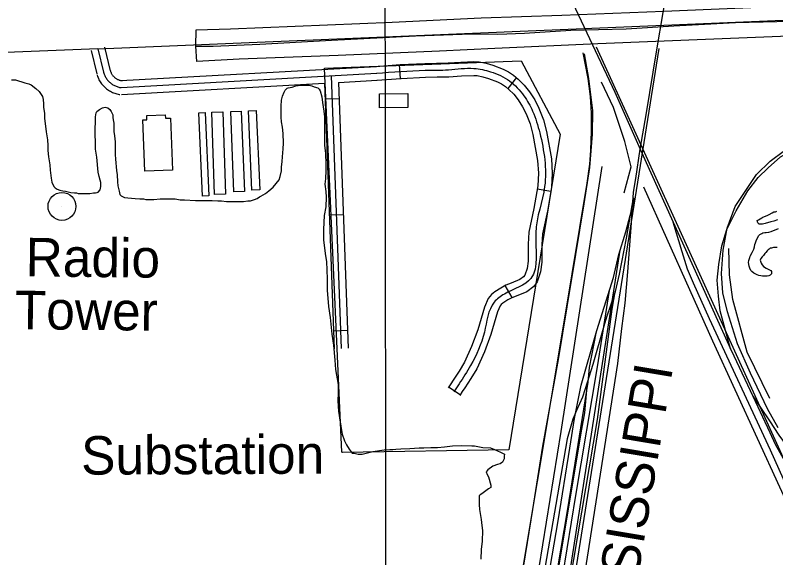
# Model space of a CAD drawing. Extents: x 3313442 to 3351311, y 721974 to 747360.
# Drawn here: x 3327267 to 3328908, y 733684 to 734854 of the extents above; entities that cross this region are included whole.
import ezdxf

# ---------------------------------------------------------------- set-up
doc = ezdxf.new("R2010")
doc.units = 0
for name, color, linetype in [('V-BLDG-OTLN', 7, 'Continuous'), ('V-BRDG-OTLN', 7, 'Continuous'), ('V-GRID-MAJR', 7, 'Continuous'), ('V-RAIL-IDEN', 7, 'Continuous'), ('V-RAIL-TRAK', 7, 'Continuous'), ('V-ROAD-CNTR', 7, 'Continuous'), ('V-SITE-OTLN', 7, 'Continuous'), ('V-SITE-OTLN-IDEN', 7, 'Continuous'), ('V-SITE-VEGE', 7, 'Continuous'), ('V-TOPO-SHOR', 7, 'Continuous'), ('V-TOPO-TOWR', 7, 'Continuous'), ('V-TOPO-TOWR-IDEN', 7, 'Continuous')]:
    doc.layers.add(name, color=color, linetype=linetype)

msp = doc.modelspace()

# ---------------------------------------------------------------- linework, layer by layer
at = {"layer": 'V-BLDG-OTLN'}
for points in [[(3328114, 734684.9), (3328114.2, 734654.7), (3328052.9, 734654.2), (3328052.7, 734684.4)], [(3327546.9, 734517.8), (3327542.7, 734628.2), (3327551.1, 734628.5), (3327550.7, 734637.5), (3327590.9, 734639.1), (3327591.2, 734631.5), (3327602, 734631.9), (3327606.3, 734520.1)], [(3327670.8, 734463.6), (3327662.9, 734643.6), (3327676.7, 734644.2), (3327684.5, 734464.2)], [(3327697, 734467.4), (3327691.5, 734644.6), (3327715.3, 734645.3), (3327720.8, 734468.1)], [(3327738.9, 734473.1), (3327732, 734646.4), (3327754.8, 734647.3), (3327761.8, 734474)], [(3327777.5, 734476.8), (3327770.1, 734647.8), (3327787.2, 734648.5), (3327794.6, 734477.6)]]:
    msp.add_lwpolyline(points, close=True, dxfattribs=at)
at = {"layer": 'V-BRDG-OTLN'}
msp.add_lwpolyline([(3329200.4, 734803.9), (3329188.2, 734806.1), (3329102.4, 734812.3), (3328989.8, 734811), (3328774.2, 734802.1), (3328523.7, 734792.1), (3328302, 734782), (3328182.3, 734776.6), (3327963.6, 734766.7), (3327750.4, 734759.3), (3327658.7, 734754.3), (3327656.9, 734786.7), (3327657.2, 734821.9), (3327731.8, 734824.5), (3328080.2, 734838.7), (3328272.4, 734847.9), (3328446.3, 734853.9), (3328666.4, 734862.3), (3328887.9, 734871.5), (3329054.7, 734876), (3329202.8, 734875.2), (3329202.4, 734839.7)], close=True, dxfattribs=at)
msp.add_lwpolyline([(3327657, 734786.7), (3327663.3, 734787), (3327694.3, 734787), (3327794.7, 734791.3), (3327949.7, 734800.3), (3328130.6, 734809), (3328251.3, 734813.3), (3328308.1, 734813.2), (3328365.7, 734815), (3328465.8, 734821.5), (3328585, 734824.7), (3328687.6, 734830.8), (3328821.2, 734837.7), (3328910.2, 734840.5), (3328975.9, 734841.5), (3329049.7, 734843.6), (3329118, 734842.1), (3329191.5, 734840.1), (3329202.2, 734839.7)], dxfattribs=at)
at = {"layer": 'V-GRID-MAJR'}
msp.add_spline([(3328075.1, 727366.3), (3328067.1, 733424.9), (3328059.2, 739486.7), (3328051.3, 745548.5), (3328051.3, 745551.5)], degree=3, dxfattribs=at)
at = {"layer": 'V-RAIL-TRAK'}
msp.add_line((3328555.1, 734220.1), (3328561, 734257.6), dxfattribs=at)
for points in [[(3328599.8, 734460.5), (3328600.7, 734472.2), (3328605.9, 734501.7), (3328615.5, 734565), (3328628.9, 734643.6), (3328650.8, 734774.6), (3328680.6, 734953.6), (3328726.3, 735228.9), (3328788, 735605.3), (3328838.6, 735905.7), (3328862.8, 736058.5), (3328890.3, 736217.5)], [(3328445.4, 734932.1), (3328560.7, 734688), (3328615.5, 734565), (3328638.3, 734513.7), (3328686.7, 734407.4), (3328723.4, 734326.8), (3328810.3, 734135)], [(3328193.5, 732625.7), (3328212.7, 732754.8), (3328229.5, 732857.7), (3328364.5, 733672.5), (3328452.6, 734200.6), (3328500.9, 734491.4), (3328506.5, 734532.8), (3328508.8, 734562.6), (3328510.3, 734603.6), (3328510, 734642.4), (3328507.8, 734678.2), (3328503.4, 734717.3), (3328492.4, 734772.7)], [(3328810.3, 734135), (3328787.8, 734216.3), (3328784.2, 734248.4), (3328781.7, 734282.7), (3328784.7, 734316.7), (3328791.7, 734356.9), (3328802.1, 734391.6), (3328822.1, 734432.1), (3328847.6, 734474.9), (3328870.1, 734503.7), (3328891.6, 734524.7), (3328917.8, 734548.3), (3328954, 734568.5), (3328990.9, 734584.7), (3329023.8, 734595.4), (3329047.1, 734599.4), (3329081.8, 734603.8), (3329124.2, 734607.5), (3329394.8, 734613.8)], [(3328307.8, 732543.9), (3328314.9, 732589), (3328364.3, 732880.5), (3328424.7, 733228.1), (3328483.2, 733566.1), (3328567, 734102.8), (3328576, 734178.4), (3328582.7, 734233.4), (3328589, 734300.6), (3328596.5, 734406.5), (3328598.8, 734446), (3328599.8, 734460.5)], [(3328599.8, 734460.5), (3328585, 734373.4), (3328570.1, 734295.5), (3328561.2, 734258.3), (3328561, 734257.6), (3328542.7, 734202.9), (3328537.1, 734183.8), (3328513, 734101.1), (3328501, 734062.1)], [(3329141.2, 733378.9), (3329128.8, 733406.2), (3329027.6, 733624.4), (3328896.2, 733916.2), (3328765.1, 734199.1), (3328730.1, 734275.9), (3328717.6, 734306.2), (3328705.5, 734343.5), (3328686.7, 734407.4)], [(3328203.5, 732092.2), (3328226.4, 732216.7), (3328228.8, 732229.9), (3328244.4, 732323.6), (3328261.5, 732426.6), (3328323.3, 732818.5), (3328429.4, 733429.6), (3328523.1, 733982.4), (3328555.1, 734220.1)], [(3328810.3, 734135), (3328817.2, 734119.6), (3328858.3, 734032.5)], [(3328501, 734062.1), (3328491.2, 734030.2), (3328478.2, 734001.7), (3328469.7, 733983.3), (3328457.6, 733940.9), (3328295.7, 733004.8), (3328243.2, 732687.4), (3328233.9, 732532.7), (3328228.6, 732476.2), (3328224, 732410), (3328223.8, 732406.5), (3328219.2, 732330.5), (3328214.3, 732253), (3328213.4, 732239.7)], [(3328501, 734062.1), (3328495, 733996.4), (3328489, 733961.3), (3328369.3, 733245.8), (3328276.3, 732676), (3328224, 732410)], [(3328858.3, 734032.5), (3328895.3, 733954.2), (3328906.3, 733929.5)], [(3328858.3, 734032.5), (3328894.4, 733979.3), (3328914.7, 733948.3), (3328936.1, 733919.1), (3328956.7, 733892.1), (3328981.4, 733867), (3329007.6, 733845.5), (3329033.8, 733826.3), (3329055.2, 733811.2), (3329083.6, 733793), (3329107.5, 733779), (3329139.3, 733763.1), (3329171, 733750.8), (3329200.9, 733740.5), (3329234.5, 733731.2), (3329270.6, 733723.8), (3329300.5, 733718.9), (3329335.9, 733716.3), (3329368.4, 733713.3), (3329492.1, 733718.3), (3329775.2, 733728)], [(3328906.3, 733929.5), (3328960.7, 733833), (3329108.3, 733519.1), (3329139.6, 733452.6), (3329184.5, 733353.3), (3329343.2, 733006.1), (3329494.1, 732673.4), (3329502.6, 732652), (3329513.6, 732622.4), (3329533.5, 732564.1), (3329539.4, 732532.7)]]:
    msp.add_lwpolyline(points, dxfattribs=at)
at = {"layer": 'V-ROAD-CNTR'}
for p, q in [((3328095.1, 734747.1), (3328097.3, 734717.2)), ((3328348.3, 734719.5), (3328329.5, 734696)), ((3327965.5, 734673.6), (3327935.5, 734672.5)), ((3328422.5, 734473.9), (3328393, 734479.1)), ((3327974.6, 734423.8), (3327944.7, 734422.7)), ((3328339.1, 734245.1), (3328324.3, 734271.2)), ((3327983.7, 734174), (3327953.8, 734172.9)), ((3328227.1, 734035.6), (3328202.1, 734052.3))]:
    msp.add_line(p, q, dxfattribs=at)
for points in [[(3327445.3, 734781.4), (3329181.9, 734853.6)], [(3327445.3, 734781.4), (3325663.8, 734710.1), (3324415, 734655.9)], [(3327445.3, 734781.4), (3327457.6, 734730.7)], [(3327459.9, 734785), (3327472.1, 734734.2)], [(3327896.4, 730170.4), (3328023.8, 730890.7), (3328416, 733278.4), (3328655.9, 734782.1)], [(3329577.9, 732463.1), (3328589, 734637), (3328521.3, 734784.9)], [(3327430.7, 734777.9), (3327443, 734727.2)], [(3328494.4, 734770.4), (3328503.7, 734717.6), (3328512.4, 734648.4), (3328511.6, 734597.4), (3328505.7, 734525.7), (3328493.6, 734447.1), (3328475.5, 734338.2), (3328456.7, 734225), (3328438.1, 734112), (3328404.6, 733924.8), (3328383.2, 733788.7), (3328352.4, 733597.3)], [(3328045.2, 734743.5), (3328097.8, 734747.3), (3328150.7, 734750), (3328176.2, 734750.7), (3328201.4, 734751.3), (3328228.5, 734752.7), (3328256.6, 734754.2), (3328267.6, 734753.6), (3328283, 734750.4), (3328297.6, 734746), (3328320, 734737.3), (3328331.3, 734731.4), (3328342.2, 734724.3), (3328352.3, 734716.2), (3328365.3, 734703.2), (3328376.6, 734688.8), (3328387.7, 734671.6), (3328397, 734653.3), (3328406.4, 734628.6), (3328413.4, 734603.2), (3328423.7, 734544), (3328425.6, 734513.4), (3328424.1, 734482.9), (3328415, 734431.6), (3328404.9, 734382.2), (3328403.3, 734359.2), (3328403.3, 734321.5), (3328400.5, 734300.6), (3328393, 734279.4), (3328385.8, 734268.8), (3328370.8, 734257.6), (3328348, 734248.5), (3328338.4, 734244.7), (3328330.1, 734240), (3328319.1, 734233), (3328315.6, 734230.1), (3328313.4, 734227.4), (3328307.4, 734214.3), (3328293.4, 734165.9), (3328279.4, 734128.3), (3328262.7, 734091.6), (3328250, 734070.6), (3328237.2, 734050.9), (3328231.6, 734042.4), (3328225.9, 734033.9)], [(3327471.9, 734735.1), (3327472.4, 734733.5), (3327472.8, 734732.3), (3327473.3, 734731.1), (3327473.8, 734730), (3327474.4, 734728.8), (3327475, 734727.7), (3327475.7, 734726.6), (3327476.4, 734725.5), (3327477.2, 734724.5), (3327478, 734723.4), (3327478.8, 734722.5), (3327479.7, 734721.5), (3327480.6, 734720.6), (3327481.6, 734719.8), (3327482.6, 734719), (3327483.6, 734718.2), (3327484.7, 734717.4), (3327485.8, 734716.8), (3327486.9, 734716.1), (3327488, 734715.5), (3327489.2, 734715), (3327490.4, 734714.5), (3327491.6, 734714), (3327492.8, 734713.6), (3327494.1, 734713.3), (3327495.3, 734713), (3327496.6, 734712.7), (3327497.7, 734712.6)], [(3327494.6, 734712.7), (3328046.1, 734743.5)], [(3327443.2, 734726.3), (3327443.9, 734724.2), (3327444.7, 734721.8), (3327445.7, 734719.4), (3327446.7, 734717.1), (3327447.8, 734714.8), (3327449.1, 734712.6), (3327450.4, 734710.4), (3327451.8, 734708.3), (3327453.3, 734706.2), (3327454.9, 734704.3), (3327456.6, 734702.3), (3327458.3, 734700.5), (3327460.1, 734698.7), (3327462, 734697), (3327464, 734695.4), (3327466, 734693.9), (3327468.1, 734692.4), (3327470.3, 734691.1), (3327472.5, 734689.8), (3327474.7, 734688.6), (3327477, 734687.5), (3327479.4, 734686.6), (3327481.8, 734685.7), (3327484.2, 734684.9), (3327486.6, 734684.2), (3327489.1, 734683.6), (3327491.5, 734683.2), (3327493.1, 734682.9)], [(3327457.6, 734730.7), (3327458.1, 734728.8), (3327458.8, 734727), (3327459.5, 734725.3), (3327460.3, 734723.5), (3327461.1, 734721.8), (3327462, 734720.1), (3327463, 734718.5), (3327464.1, 734716.9), (3327465.2, 734715.3), (3327466.4, 734713.8), (3327467.7, 734712.4), (3327469, 734711), (3327470.4, 734709.7), (3327471.8, 734708.4), (3327473.3, 734707.2), (3327474.8, 734706), (3327476.4, 734704.9), (3327478, 734703.9), (3327479.7, 734702.9), (3327481.4, 734702.1), (3327483.1, 734701.2), (3327484.9, 734700.5), (3327486.7, 734699.8), (3327488.5, 734699.3), (3327490.3, 734698.7), (3327492.2, 734698.3), (3327494.1, 734697.9), (3327495.4, 734697.7)], [(3327495.4, 734697.7), (3328046.9, 734728.5)], [(3327948.7, 734723.1), (3327970.1, 734135.5)], [(3328047.4, 734713.5), (3328099.7, 734717.3), (3328151.9, 734720), (3328177, 734720.7), (3328202.6, 734721.3), (3328230.1, 734722.8), (3328256.6, 734724.1), (3328263.8, 734723.8), (3328275.5, 734721.3), (3328287.8, 734717.6), (3328307.6, 734710), (3328316.1, 734705.5), (3328324.6, 734700), (3328332.2, 734693.8), (3328342.8, 734683.3), (3328352.2, 734671.3), (3328361.7, 734656.6), (3328369.5, 734641.2), (3328377.8, 734619.3), (3328384, 734596.6), (3328393.9, 734540.4), (3328395.6, 734513.2), (3328394.3, 734486.3), (3328385.6, 734437.2), (3328375.1, 734386.3), (3328373.3, 734360.2), (3328373.3, 734323.5), (3328371.2, 734307.7), (3328366.1, 734293.2), (3328363.8, 734289.9), (3328356, 734284), (3328336.9, 734276.3), (3328325.4, 734271.8), (3328314.6, 734265.7), (3328301.6, 734257.4), (3328294.2, 734251.5), (3328287.6, 734243.2), (3328279.2, 734224.8), (3328264.9, 734175.3), (3328251.7, 734139.8), (3328236.1, 734105.6), (3328224.6, 734086.6), (3328212.1, 734067.3), (3328206.6, 734059), (3328201, 734050.6)], [(3327496.2, 734682.8), (3327934.3, 734707.2)], [(3327934.3, 734707.2), (3327955.1, 734134.9)], [(3327964.2, 734708.9), (3328047.8, 734713.6)], [(3327964.2, 734708.9), (3327985.1, 734136)], [(3328912.8, 733964.5), (3328890.2, 734005.6), (3328853.4, 734082.4), (3328825.3, 734145.2), (3328803.7, 734214.3), (3328793.5, 734255.2), (3328790.5, 734296.8), (3328794.3, 734347), (3328802.8, 734394.8), (3328820.4, 734441.8), (3328847.2, 734482.2), (3328866.5, 734510.6), (3328895.5, 734538.9), (3328926.8, 734562)], [(3327962.4, 730543.7), (3327970.5, 730696.8), (3327985.7, 730796.8), (3328034.3, 731082.1), (3328099.6, 731452.5), (3328175.5, 731923.7), (3328203.3, 732086.2), (3328211.4, 732182.2), (3328220.6, 732304.3), (3328231.1, 732438.6), (3328237.5, 732535.4), (3328252.3, 732631.4), (3328363.9, 733327.8), (3328438.6, 733764.2), (3328463.2, 733920.8), (3328473.5, 733984.2), (3328487.8, 734056.2), (3328522.1, 734174), (3328557.7, 734288.4), (3328569.1, 734337.7), (3328584.6, 734387), (3328603.8, 734460.3)], [(3328206.5, 732124.6), (3328291.9, 732618.4), (3328337, 732892.9), (3328390.9, 733218.1), (3328451.6, 733573), (3328572.2, 734347.5)], [(3328220.6, 732303.5), (3328258, 732503), (3328291.8, 732701.8), (3328327.5, 732915.5), (3328370.9, 733177.4), (3328430, 733530.9), (3328476.2, 733818.3), (3328522.9, 734095.9), (3328549, 734260.6)], [(3328231.3, 732440.7), (3328233.5, 732440.6), (3328251.8, 732544.6), (3328297, 732817.8), (3328350.1, 733143.6), (3328405.4, 733471.9), (3328458.9, 733789.5), (3328503.1, 734062.6), (3328506.2, 734094.3), (3328521.4, 734171.7)]]:
    msp.add_lwpolyline(points, dxfattribs=at)
msp.add_spline([(3328046.3, 734728.5), (3328151.3, 734735), (3328202, 734736.3), (3328256.6, 734739.2), (3328292.7, 734731.8), (3328333.4, 734712.1), (3328364.4, 734680), (3328383.2, 734647.2), (3328398.7, 734599.9), (3328409.2, 734484.6), (3328390, 734384.2), (3328379.6, 734286.3), (3328322.3, 734252.8), (3328300.5, 734235.3), (3328279.1, 734170.6), (3328249.4, 734098.6), (3328224.6, 734059.1), (3328213.5, 734042.3)], degree=3, dxfattribs=at)
at = {"layer": 'V-SITE-OTLN'}
msp.add_lwpolyline([(3327973.2, 733910.9), (3327971.6, 733912.1), (3327934.1, 734739.6), (3328358.8, 734755.7), (3328442.4, 734597.7), (3328331.9, 733917.3)], close=True, dxfattribs=at)
at = {"layer": 'V-SITE-VEGE'}
for points in [[(3327258.8, 734714.4), (3327267.9, 734714.4), (3327288, 734708.3), (3327296.5, 734705.8), (3327301.3, 734703.4), (3327311.7, 734695.5), (3327319, 734689.4), (3327326.2, 734678.4), (3327327.5, 734672.3), (3327328.1, 734662.6), (3327328, 734655.9), (3327329.9, 734641.9), (3327330.4, 734631.6), (3327333.5, 734602.3), (3327336.5, 734585.3), (3327337.7, 734573.1), (3327337.7, 734562.2), (3327338.9, 734548.8), (3327341.9, 734531.2), (3327342.5, 734519.6), (3327344.3, 734502.6), (3327346.1, 734494), (3327350.3, 734484.3), (3327353.4, 734481.9), (3327357.6, 734478.8), (3327363.1, 734477), (3327369.8, 734475.2), (3327375.3, 734474.5), (3327386.8, 734471.5), (3327394.7, 734470.9), (3327399, 734470.9)], [(3327399, 734470.9), (3327402.7, 734469.6), (3327428.2, 734469.6), (3327436.1, 734470.8), (3327440.4, 734470.8), (3327444, 734471.4), (3327445.8, 734472.6), (3327450.1, 734477.5), (3327451.9, 734484.8), (3327452, 734493.3), (3327450.1, 734498.2), (3327448.3, 734506.1), (3327445.9, 734515.2), (3327442.9, 734547.5), (3327440.5, 734565.1), (3327440.5, 734578.5), (3327439.9, 734598), (3327440, 734634.5), (3327441.8, 734643), (3327443, 734646), (3327449.1, 734650.3), (3327455.2, 734653.9), (3327461.3, 734655.7), (3327463.7, 734655.1), (3327466.8, 734653.9), (3327471, 734650.2), (3327474, 734646), (3327477.7, 734639.3), (3327477.7, 734633.2), (3327478.3, 734628.3), (3327479.5, 734621), (3327480.1, 734610.7), (3327480.1, 734603.4), (3327481.3, 734593.7), (3327482.5, 734580.9), (3327482.4, 734553.5), (3327483.7, 734543.2), (3327485.4, 734518.8), (3327487.3, 734509.7), (3327487.9, 734494.5), (3327488.5, 734486), (3327491.5, 734474.4), (3327492.7, 734467.1), (3327495.7, 734464.1), (3327498.2, 734462.8), (3327503, 734461), (3327510.3, 734460.4), (3327525.5, 734458.5), (3327535.9, 734457.9), (3327543.8, 734457.9), (3327548.6, 734456.7), (3327566.3, 734456.7), (3327579.7, 734457.9), (3327611.9, 734457.8), (3327622.9, 734456), (3327632.6, 734456), (3327656.3, 734454.1), (3327691.6, 734454.1), (3327704.4, 734453.5), (3327712.3, 734453.4), (3327722.6, 734452.2), (3327759.7, 734452.2), (3327768.9, 734453.4), (3327774.3, 734454), (3327783.5, 734456.4), (3327789, 734458.8), (3327793.8, 734462.5), (3327796.9, 734463.7), (3327807.2, 734469.2), (3327813.9, 734475.2), (3327823.7, 734483.1), (3327836.5, 734498.9), (3327838.9, 734506.2), (3327841.3, 734518.4), (3327841.4, 734526.3), (3327843.2, 734538.5), (3327843.8, 734548.8), (3327845.1, 734565.8), (3327845.7, 734578), (3327845.1, 734598.7), (3327843.9, 734612.1), (3327841.5, 734623.6), (3327840.9, 734634), (3327840.9, 734657.7), (3327841.5, 734670.5), (3327843.4, 734679.6), (3327847, 734688.1), (3327849.5, 734692.4), (3327853.7, 734696.6), (3327856.2, 734697.2), (3327864.7, 734699), (3327872.6, 734701.5), (3327882.3, 734703.3), (3327892.7, 734703.3), (3327901.2, 734702.7), (3327907.3, 734701.4), (3327912.1, 734699.6), (3327920, 734697.2), (3327922.5, 734694.7), (3327924.9, 734690.5), (3327928.5, 734677.7)], [(3327928.5, 734677.7), (3327930.3, 734665.5), (3327932.8, 734647.3), (3327934.6, 734634.5), (3327934.5, 734573.6), (3327936.3, 734556), (3327936.9, 734532.9), (3327936.9, 734518.9), (3327936.2, 734501.2), (3327935, 734489.7), (3327936.8, 734473.9), (3327938, 734461.7), (3327936.8, 734441), (3327933.7, 734422.2), (3327932.4, 734391.7), (3327932.4, 734368.6), (3327936.6, 734335.2), (3327938.4, 734323), (3327940.2, 734285.3), (3327940.2, 734260.9), (3327942.6, 734225.6), (3327946.8, 734202.5), (3327950.4, 734166.6), (3327953.4, 734142.9), (3327956.4, 734110.6), (3327958.2, 734090), (3327963.7, 734057.7), (3327963.7, 734040.1), (3327963, 734022.4), (3327964.8, 734000.5), (3327966.6, 733985.9), (3327969.7, 733968.3), (3327970.9, 733959.1), (3327972.7, 733950.6), (3327977.5, 733936.6), (3327981.8, 733927.5), (3327987.2, 733918.4), (3327993.9, 733909.8), (3327998.2, 733909.8), (3328006.7, 733908), (3328015.2, 733908), (3328038.3, 733913.4), (3328063.3, 733917), (3328075.5, 733917.6), (3328081.5, 733917.6), (3328088.2, 733918.2), (3328098.6, 733919.4), (3328118.6, 733920), (3328138.7, 733921.2), (3328148.5, 733921.2), (3328163.7, 733921.8), (3328178.3, 733921.8), (3328192.9, 733923.6), (3328210.5, 733925.4), (3328228.8, 733926), (3328251.9, 733925.3), (3328258, 733925.3), (3328276.2, 733922.3), (3328292.6, 733921), (3328301.2, 733918), (3328313.9, 733911.9), (3328319.4, 733909.4), (3328322.4, 733907.6), (3328321.8, 733903.4), (3328321.8, 733897.3), (3328318.2, 733890.6), (3328313.3, 733886.9), (3328307.8, 733885.7), (3328297.5, 733882.1), (3328286.5, 733874.2), (3328282.8, 733869.3), (3328285.3, 733863.9), (3328288.3, 733859), (3328293.2, 733840.7), (3328293.1, 733835.9), (3328288.3, 733832.8), (3328273.7, 733822.5), (3328270, 733820.1), (3328268.2, 733818.2), (3328268.2, 733799.4), (3328268.8, 733788.4), (3328270.6, 733775.7), (3328272.4, 733766.5), (3328273.6, 733753.7), (3328274.8, 733742.8), (3328274.1, 733720.3), (3328272.3, 733702), (3328271.7, 733681.4)], [(3328911.8, 734413), (3328903.6, 734410.2), (3328897, 734408.3), (3328884.9, 734405), (3328878.8, 734403.6), (3328874.4, 734403.4), (3328871.7, 734403.4), (3328868.9, 734406.1), (3328867.6, 734411.1), (3328870.3, 734413), (3328877.7, 734416.8), (3328880.2, 734418.5), (3328883.5, 734419.6), (3328889, 734422.3), (3328893.7, 734424.5), (3328899.8, 734427.8), (3328903.6, 734429.7), (3328907.5, 734430.3), (3328910.2, 734431.7)], [(3328898.6, 734351.9), (3328895.8, 734351.4), (3328893.6, 734349.2), (3328891.1, 734347.8), (3328889.2, 734345.9), (3328886.2, 734342.3), (3328884.5, 734340.1), (3328881, 734336), (3328878.7, 734333.3), (3328875.4, 734329.4), (3328874.3, 734326.1), (3328876, 734319.5), (3328878.2, 734315.4), (3328881.5, 734312.4), (3328887, 734308.3), (3328893, 734305.5), (3328896.9, 734303.6), (3328898.8, 734301.1), (3328898.8, 734296.4), (3328896, 734293.7), (3328893, 734292.3), (3328889.1, 734291.5), (3328879.5, 734291.5), (3328875.9, 734291.8), (3328871.6, 734292.6), (3328867.7, 734294.3), (3328862.2, 734297.3), (3328860.3, 734298.1), (3328856.2, 734301.1), (3328854.2, 734303.6), (3328851.8, 734308.6), (3328850.4, 734313), (3328849, 734320.7), (3328849.6, 734325.3), (3328851.5, 734331.4), (3328852.9, 734334.7), (3328857, 734342.6), (3328860.3, 734349.8), (3328862, 734354.7), (3328862.8, 734359.4), (3328863.9, 734363.3), (3328866.4, 734369.3), (3328871.4, 734378.9), (3328873.6, 734381.1), (3328878, 734383.6), (3328880.2, 734384.4), (3328884.3, 734385.2), (3328887.1, 734385.2), (3328892.8, 734385.8), (3328897.8, 734387.4), (3328914, 734394)], [(3328910.9, 734352.8), (3328906.3, 734353.3), (3328903.2, 734353.3), (3328898.6, 734351.9)]]:
    msp.add_lwpolyline(points, dxfattribs=at)
at = {"layer": 'V-TOPO-SHOR'}
for points in [[(3328580.8, 734471.2), (3328595.5, 734527.3), (3328582.5, 734581.8), (3328557.8, 734655.1), (3328531.9, 734709.4)], [(3328532.8, 734527.5), (3328444.3, 733956.3), (3328349.3, 733370.6)], [(3328622.4, 734484), (3328771.4, 734151.7), (3329060.3, 733522.9)], [(3328895.3, 734027.8), (3328846.3, 734127.7), (3328814.9, 734241.2), (3328808, 734294.3), (3328806.7, 734350.9)]]:
    msp.add_lwpolyline(points, dxfattribs=at)
at = {"layer": 'V-TOPO-TOWR'}
msp.add_line((3327367.9, 734441.6), (3327367.9, 734441.6), dxfattribs=at)
msp.add_circle((3327367.9, 734441.6), 30, dxfattribs=at)

# ---------------------------------------------------------------- texts
at = {"layer": 'V-RAIL-IDEN'}
msp.add_text('MISSISSIPPI', height=83, rotation=80.4701, dxfattribs=at).set_placement((3328577.2, 733443.8))
at = {"layer": 'V-SITE-OTLN-IDEN'}
msp.add_text('Substation', height=83, rotation=0.2566, dxfattribs=at).set_placement((3327409.4, 733863.4))
at = {"layer": 'V-TOPO-TOWR-IDEN'}
for s, p in [('Radio', (3327289.2, 734291.1)), ('Tower', (3327265.8, 734177.2))]:
    msp.add_text(s, height=83, rotation=359.3568, dxfattribs=at).set_placement(p)

doc.saveas('drawing.dxf')
